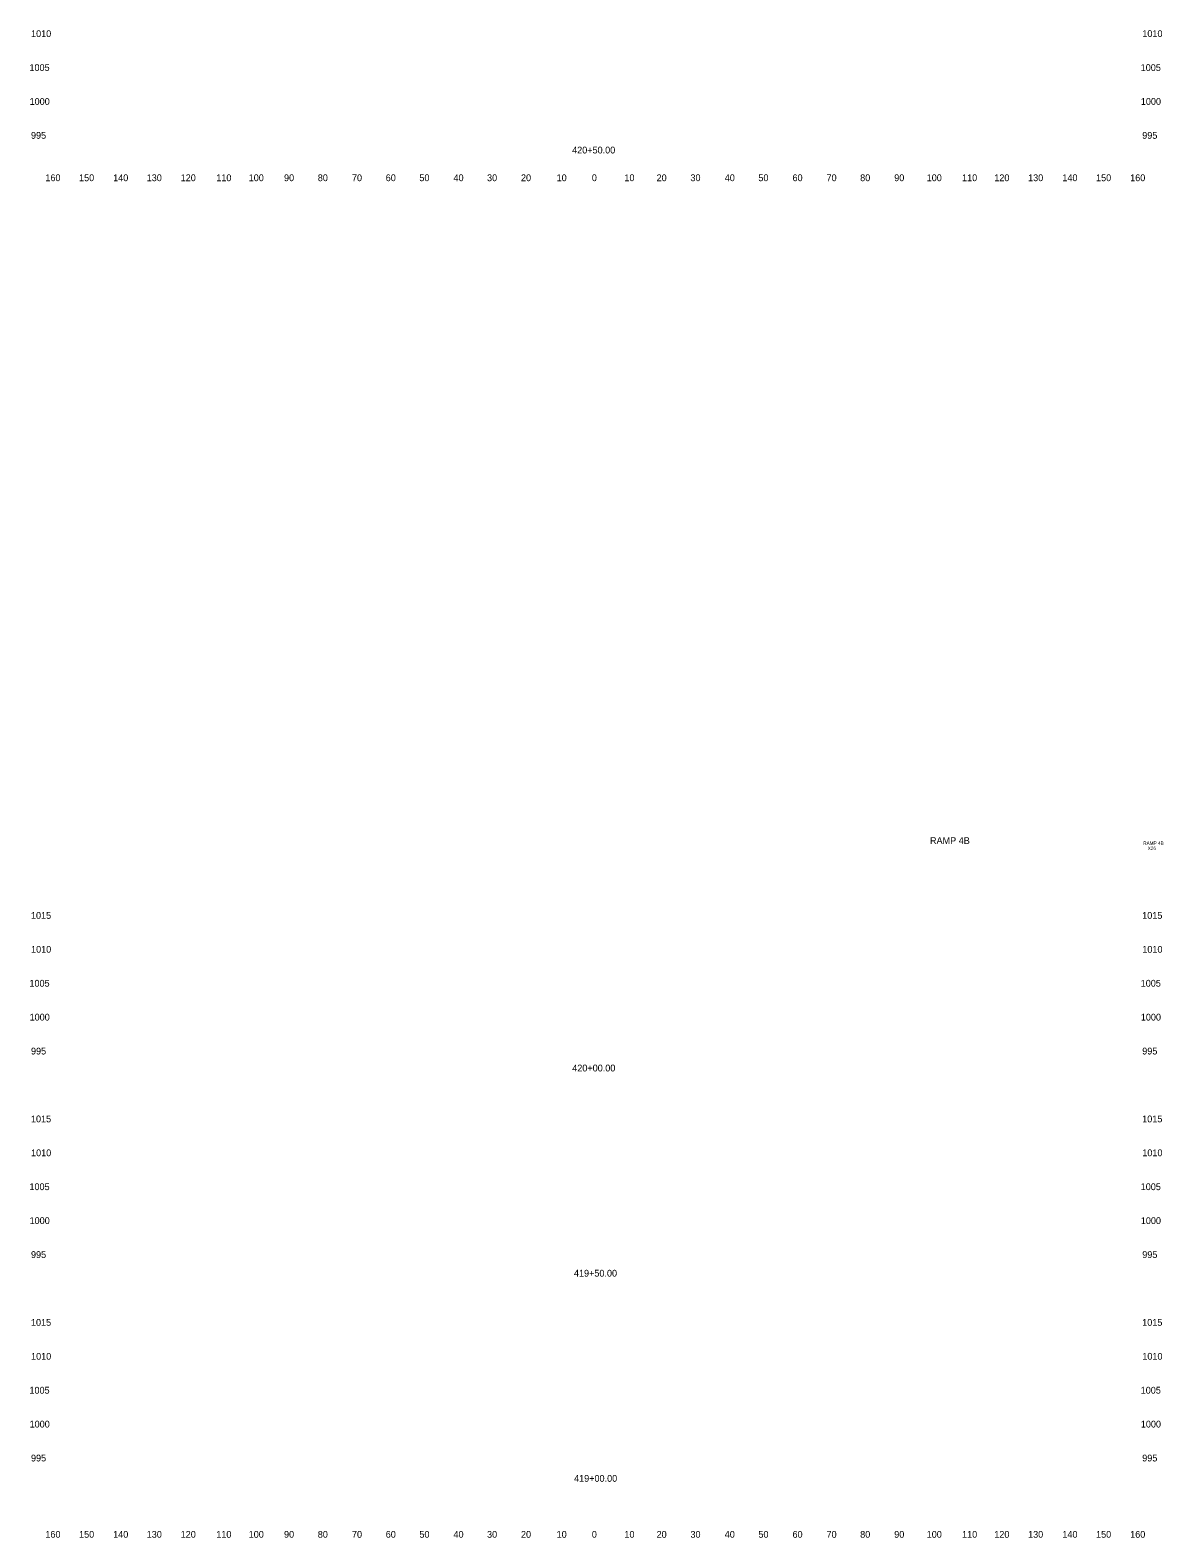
# Model space of a CAD drawing. Extents: x 4994 to 6358, y 4997 to 8804.
# Drawn here: x 6023.6 to 6357.7, y 6997.5 to 7442 of the extents above; entities that cross this region are included whole.
import ezdxf

# ---------------------------------------------------------------- set-up
doc = ezdxf.new("R2010")
doc.units = 0
for name, color, linetype in [('CLS_Search_Dist', 7, 'Continuous'), ('RD_XE_Ground', 7, 'Continuous'), ('UC_PD_Text', 7, 'Continuous')]:
    doc.layers.add(name, color=color, linetype=linetype)

msp = doc.modelspace()

# ---------------------------------------------------------------- texts
at = {"layer": 'CLS_Search_Dist'}
for s, p in [('1010', (6023.88, 7440)), ('1010', (6351.68, 7440)), ('1005', (6023.4, 7430)), ('1005', (6351.2, 7430)), ('1000', (6023.44, 7420)), ('1000', (6351.24, 7420)), ('995', (6023.86, 7410)), ('995', (6351.66, 7410)), ('160', (6028.1, 7397.5)), ('150', (6038.04, 7397.5)), ('140', (6048.1, 7397.5)), ('130', (6057.99, 7397.5)), ('120', (6068.01, 7397.5)), ('110', (6078.51, 7397.5)), ('100', (6088.07, 7397.5)), ('90', (6098.5, 7397.5)), ('80', (6108.46, 7397.5)), ('70', (6118.54, 7397.5)), ('60', (6128.5, 7397.5)), ('50', (6138.43, 7397.5)), ('40', (6148.5, 7397.5)), ('30', (6158.39, 7397.5)), ('20', (6168.4, 7397.5)), ('10', (6178.91, 7397.5)), ('0', (6189.3, 7397.5)), ('0', (6189.3, 7397.5)), ('10', (6198.91, 7397.5)), ('20', (6208.4, 7397.5)), ('30', (6218.39, 7397.5)), ('40', (6228.5, 7397.5)), ('50', (6238.43, 7397.5)), ('60', (6248.5, 7397.5)), ('70', (6258.54, 7397.5)), ('80', (6268.46, 7397.5)), ('90', (6278.5, 7397.5)), ('100', (6288.07, 7397.5)), ('110', (6298.51, 7397.5)), ('120', (6308.01, 7397.5)), ('130', (6317.99, 7397.5)), ('140', (6328.1, 7397.5)), ('150', (6338.04, 7397.5)), ('160', (6348.1, 7397.5)), ('1015', (6023.85, 7180)), ('1015', (6351.65, 7180)), ('1010', (6023.88, 7170)), ('1010', (6351.68, 7170)), ('1005', (6023.4, 7160)), ('1005', (6351.2, 7160)), ('1000', (6023.44, 7150)), ('1000', (6351.24, 7150)), ('995', (6023.86, 7140)), ('995', (6351.66, 7140)), ('1015', (6023.85, 7120)), ('1015', (6351.65, 7120)), ('1010', (6023.88, 7110)), ('1010', (6351.68, 7110)), ('1005', (6023.4, 7100)), ('1005', (6351.2, 7100)), ('1000', (6023.44, 7090)), ('1000', (6351.24, 7090)), ('995', (6023.86, 7080)), ('995', (6351.66, 7080)), ('1015', (6023.85, 7060)), ('1015', (6351.65, 7060)), ('1010', (6023.88, 7050)), ('1010', (6351.68, 7050)), ('1005', (6023.4, 7040)), ('1005', (6351.2, 7040)), ('1000', (6023.44, 7030)), ('1000', (6351.24, 7030)), ('995', (6023.86, 7020)), ('995', (6351.66, 7020)), ('160', (6028.1, 6997.5)), ('150', (6038.04, 6997.5)), ('140', (6048.1, 6997.5)), ('130', (6057.99, 6997.5)), ('120', (6068.01, 6997.5)), ('110', (6078.51, 6997.5)), ('100', (6088.07, 6997.5)), ('90', (6098.5, 6997.5)), ('80', (6108.46, 6997.5)), ('70', (6118.54, 6997.5)), ('60', (6128.5, 6997.5)), ('50', (6138.43, 6997.5)), ('40', (6148.5, 6997.5)), ('30', (6158.39, 6997.5)), ('20', (6168.4, 6997.5)), ('10', (6178.91, 6997.5)), ('0', (6189.3, 6997.5)), ('0', (6189.3, 6997.5)), ('10', (6198.91, 6997.5)), ('20', (6208.4, 6997.5)), ('30', (6218.39, 6997.5)), ('40', (6228.5, 6997.5)), ('50', (6238.43, 6997.5)), ('60', (6248.5, 6997.5)), ('70', (6258.54, 6997.5)), ('80', (6268.46, 6997.5)), ('90', (6278.5, 6997.5)), ('100', (6288.07, 6997.5)), ('110', (6298.51, 6997.5)), ('120', (6308.01, 6997.5)), ('130', (6317.99, 6997.5)), ('140', (6328.1, 6997.5)), ('150', (6338.04, 6997.5)), ('160', (6348.1, 6997.5))]:
    msp.add_text(s, height=2, dxfattribs=at).set_placement(p)
at = {"layer": 'RD_XE_Ground'}
for s, p in [('420+50.00', (6183.49, 7405.67)), ('420+00.00', (6183.52, 7135)), ('419+50.00', (6184.02, 7074.5)), ('419+00.00', (6184.06, 7014))]:
    msp.add_text(s, height=2, dxfattribs=at).set_placement(p)
at = {"layer": 'UC_PD_Text'}
for s, height, p in [('RAMP 4B', 2, (6289.05, 7202.06)), ('RAMP 4B', 1, (6351.94, 7201.8)), ('X26', 1, (6353.26, 7200.3))]:
    msp.add_text(s, height=height, dxfattribs=at).set_placement(p)

doc.saveas('drawing.dxf')
